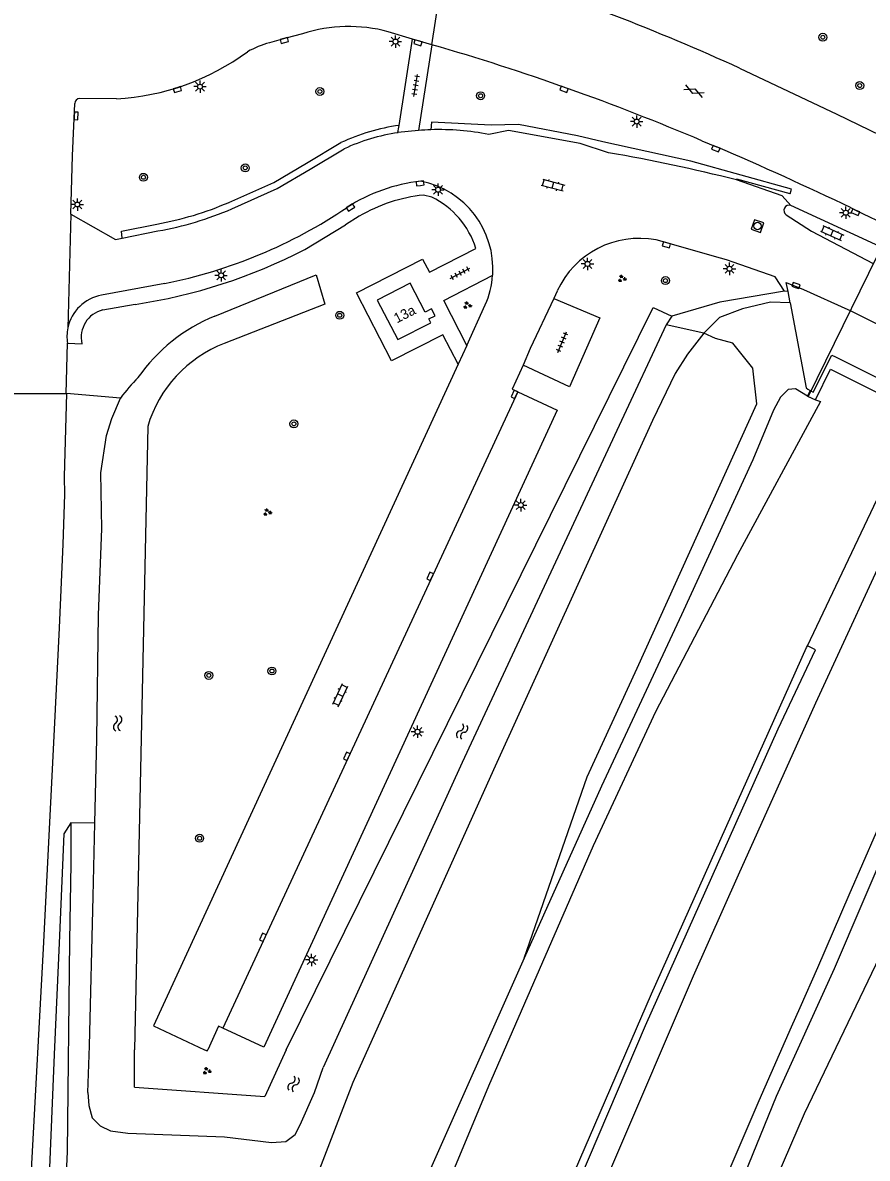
# Model space of a CAD drawing. Extents: x 137999 to 141000, y 397500 to 400501.
# Drawn here: x 138159.8 to 138245, y 398489.1 to 398603.5 of the extents above; entities that cross this region are included whole.
import ezdxf

# ---------------------------------------------------------------- set-up
doc = ezdxf.new("R2010")
doc.units = 0
for name, color, linetype in [('gg-anno-huisnummerreeks BGT', 7, 'Continuous'), ('gg-bbg-hoofdgebouw', 7, 'Continuous'), ('gg-knt-BGT kruinlijn', 7, 'Continuous'), ('gg-knt-bronhoudergrens niveau 01', 7, 'Continuous'), ('gg-knt-verharding', 7, 'Continuous'), ('gg-knt-verharding nz', 7, 'Continuous'), ('gg-kntw-bovenkant insteek waterloop', 7, 'Continuous'), ('gt-grn-groengrens', 7, 'Continuous'), ('gt-grn-weggrens', 7, 'Continuous'), ('gt-symb-boom', 7, 'Continuous'), ('gt-symb-gesloten verharding', 7, 'Continuous'), ('gt-symb-groenvak', 7, 'Continuous'), ('gt-symb-klinker verharding', 7, 'Continuous'), ('gt-symb-kolk', 7, 'Continuous'), ('gt-symb-lichtmast', 7, 'Continuous'), ('gt-symb-rioolschacht', 7, 'Continuous'), ('gt-symb-tegel verharding', 7, 'Continuous'), ('gt-symb-watersymbool', 7, 'Continuous'), ('gx-grn-maaiveld', 7, 'Continuous')]:
    doc.layers.add(name, color=color, linetype=linetype)

# ---------------------------------------------------------------- blocks, each defined once
blk = doc.blocks.new('gt0-KOLK')
at = {"layer": 'gt-symb-kolk'}
blk.add_lwpolyline([(0, 0), (0.37, 0), (0.37, 0.4), (-0.38, 0.4), (-0.38, 0), (0, 0)], dxfattribs=at)
blk = doc.blocks.new('gt0-LMAST')
at = {"layer": 'gt-symb-lichtmast'}
for p, q in [((-0.18, 0.17), (-0.45, 0.44)), ((0, 0.25), (0, 0.62)), ((0.17, 0.17), (0.44, 0.44)), ((-0.25, 0), (-0.63, 0)), ((-0.18, -0.18), (-0.45, -0.45)), ((0, -0.25), (0, -0.63)), ((0.44, -0.45), (0.17, -0.18)), ((0.25, 0), (0.62, 0))]:
    blk.add_line(p, q, dxfattribs=at)
blk.add_circle((0, 0), 0.25, dxfattribs=at)
blk = doc.blocks.new('gt0-BOOM')
at = {"layer": 'gt-symb-boom'}
for radius in [0.4, 0.2]:
    blk.add_circle((0, 0), radius, dxfattribs=at)
blk = doc.blocks.new('gt0-TEG1')
at = {"layer": 'gt-symb-tegel verharding'}
for p, q in [((-1.13, 0), (1.12, 0)), ((-0.9, -0.25), (-0.9, 0.25)), ((-0.45, -0.25), (-0.45, 0.25)), ((0, -0.25), (0, 0.25)), ((0.45, -0.25), (0.45, 0.25)), ((0.9, -0.25), (0.9, 0.25))]:
    blk.add_line(p, q, dxfattribs=at)
blk = doc.blocks.new('gt0-KL1')
at = {"layer": 'gt-symb-klinker verharding'}
for p, q in [((-1.15, 0.3), (1.15, 0.3)), ((-1, -0.3), (-1, 0.3)), ((-0.5, 0.3), (-0.5, 0.45)), ((0, -0.3), (0, 0.3)), ((0.5, 0.3), (0.5, 0.45)), ((1, -0.3), (1, 0.3)), ((-1.15, -0.3), (1.15, -0.3)), ((-0.5, -0.45), (-0.5, -0.3)), ((0.5, -0.45), (0.5, -0.3))]:
    blk.add_line(p, q, dxfattribs=at)
blk = doc.blocks.new('gt0-GESVH1')
at = {"layer": 'gt-symb-gesloten verharding'}
for p, q in [((-0.99, -0.26), (0.01, 0.24)), ((0.01, -0.26), (-0.99, 0.24)), ((0.01, 0.24), (1.01, -0.26)), ((1.01, 0.24), (0.01, -0.26))]:
    blk.add_line(p, q, dxfattribs=at)
blk = doc.blocks.new('gt0-GRVAK')
at = {"layer": 'gt-symb-groenvak'}
for p, q in [((-0.11, 0.19), (-0.23, 0.24)), ((-0.18, 0.15), (0.09, 0.15)), ((-0.09, 0.21), (-0.16, 0.32)), ((-0.05, 0.21), (-0.05, 0.39)), ((0, 0.21), (0.06, 0.32)), ((0.02, 0.19), (0.13, 0.24)), ((0.26, -0.05), (0.2, 0.06)), ((0.31, -0.05), (0.31, 0.13)), ((0.35, -0.05), (0.41, 0.06)), ((-0.24, -0.23), (-0.36, -0.18)), ((-0.32, -0.26), (-0.05, -0.26)), ((-0.23, -0.21), (-0.29, -0.09)), ((-0.18, -0.2), (-0.18, -0.02)), ((-0.14, -0.21), (-0.07, -0.09)), ((-0.12, -0.23), (0, -0.18)), ((0.24, -0.07), (0.12, -0.02)), ((0.17, -0.11), (0.44, -0.11)), ((0.37, -0.07), (0.49, -0.02))]:
    blk.add_line(p, q, dxfattribs=at)
blk = doc.blocks.new('gt0-RS')
at = {"layer": 'gt-symb-rioolschacht'}
blk.add_lwpolyline([(-0.5, -0.5), (0.5, -0.5), (0.5, 0.5), (-0.5, 0.5)], close=True, dxfattribs=at)
blk.add_circle((0, 0), 0.375, dxfattribs=at)
blk = doc.blocks.new('gt0-WA')
at = {"layer": 'gt-symb-watersymbool'}
for centre, start, end in [((-0.32, 0.02), 28.0725, 151.9275), ((0.43, 0.42), 208.0725, 331.9275), ((-0.32, -0.43), 28.0725, 151.9275), ((0.43, -0.03), 208.0725, 331.9275)]:
    blk.add_arc(centre, 0.425, start, end, dxfattribs=at)

msp = doc.modelspace()

# ---------------------------------------------------------------- linework, layer by layer
at = {"layer": 'gg-bbg-hoofdgebouw'}
msp.add_lwpolyline([(138197.65, 398571.59), (138200.97, 398573.27), (138200.77, 398573.66), (138201.41, 398573.99), (138201.04, 398574.69), (138200.4, 398574.36), (138198.9, 398577.26), (138195.57, 398575.56), (138197.65, 398571.59)], dxfattribs=at)
at = {"layer": 'gg-knt-BGT kruinlijn'}
for p, q in [((138239.49, 398566.29), (138241.37, 398570.01)), ((138241.37, 398570.01), (138241.74, 398569.83)), ((138241.74, 398569.83), (138250.7, 398565.38)), ((138236.23, 398565.78), (138235.5, 398564.47)), ((138236.98, 398566.54), (138236.23, 398565.78)), ((138237.71, 398566.62), (138236.98, 398566.54)), ((138238.95, 398565.88), (138237.71, 398566.62)), ((138239.21, 398566.45), (138238.95, 398565.88)), ((138239.21, 398566.45), (138239.27, 398566.42)), ((138239.27, 398566.42), (138239.49, 398566.29)), ((138235.5, 398564.47), (138233.42, 398559.46)), ((138233.42, 398559.46), (138226.22, 398543.85)), ((138226.22, 398543.85), (138218.17, 398526.58)), ((138218.17, 398526.58), (138210.38, 398509.23)), ((138164.68, 398522.89), (138164, 398521.77)), ((138241.67, 398508.18), (138247.8, 398522.61)), ((138164, 398521.77), (138163.56, 398511.53)), ((138163.56, 398511.53), (138163.01, 398499.51)), ((138210.38, 398509.23), (138198.18, 398481.84)), ((138235.81, 398495.33), (138241.67, 398508.18)), ((138163.01, 398499.51), (138162.34, 398483.26)), ((138229.04, 398478.7), (138235.81, 398495.33))]:
    msp.add_line(p, q, dxfattribs=at)
at = {"layer": 'gg-knt-bronhoudergrens niveau 01'}
for points in [[(138268.99, 398624.37), (138268.26, 398624.74), (138256.39, 398601.32), (138238.99, 398565.86), (138239.73, 398565.5)], [(138239.73, 398565.5), (138241.24, 398568.59), (138242.92, 398567.76), (138246.23, 398566.12), (138249.47, 398564.52), (138250.08, 398564.21)]]:
    msp.add_lwpolyline(points, dxfattribs=at)
at = {"layer": 'gg-knt-verharding'}
for p, q in [((138199.14, 398601.88), (138196.69, 398602.61)), ((138197.78, 398593.17), (138199.14, 398601.88)), ((138201.09, 398601.31), (138199.14, 398601.88)), ((138201.09, 398601.31), (138199.74, 398592.66)), ((138169.28, 398595.86), (138165.61, 398595.88)), ((138197.75, 398593), (138197.78, 398593.17)), ((138197.66, 398592.45), (138197.75, 398593)), ((138199.74, 398592.66), (138197.66, 398592.45)), ((138228.29, 398591.62), (138229.77, 398591.01)), ((138201.08, 398585.95), (138200.24, 398586.15)), ((138164.69, 398584.23), (138164.39, 398572.75)), ((138193.75, 398584.02), (138192.37, 398583.14)), ((138246.24, 398580.98), (138237.26, 398585.09)), ((138188.27, 398580.67), (138192.37, 398583.14)), ((138169.88, 398581.81), (138173.47, 398582.53)), ((138230.17, 398579.8), (138223.67, 398581.63)), ((138174.15, 398577.23), (138167.79, 398576.06)), ((138213.7, 398576.48), (138213.36, 398575.74)), ((138167.93, 398574.58), (138171.18, 398575.14)), ((138204.61, 398570.99), (138206.46, 398575.08)), ((138164.23, 398566.15), (138164.36, 398571.21)), ((138164.36, 398571.21), (138165.82, 398571.17)), ((138204.61, 398570.99), (138203.74, 398569.11))]:
    msp.add_line(p, q, dxfattribs=at)
for points in [[(138188.05, 398602.4), (138186.37, 398601.98), (138184.71, 398601.51)], [(138232.09, 398598.95), (138241.89, 398594.3), (138250.61, 398590.07), (138250.85, 398590.03)], [(138164.69, 398584.23), (138164.85, 398590.11), (138165.08, 398595.37)], [(138218.89, 398590.41), (138216.02, 398591.34), (138208.81, 398592.65), (138206.82, 398592.24)], [(138180.92, 398584.77), (138185.47, 398586.8), (138188.81, 398588.75), (138192.24, 398590.82)], [(138237.26, 398585.09), (138236.37, 398586.07), (138231.77, 398587.68)], [(138164.69, 398584.23), (138169.18, 398581.67), (138169.88, 398581.81)], [(138236.79, 398584.16), (138239.35, 398582.51), (138245.55, 398579.27)], [(138243.32, 398584.85), (138243.85, 398584.61), (138247.22, 398582.97)], [(138203.74, 398569.11), (138202.17, 398572.07), (138197, 398569.44), (138193.48, 398576.28), (138200.13, 398579.7), (138200.83, 398578.39), (138205.51, 398580.78)], [(138236.61, 398576.48), (138235.69, 398577.9), (138230.76, 398579.63), (138230.17, 398579.8)], [(138204.61, 398570.99), (138202.28, 398575.54), (138207.21, 398578.07)], [(138236.61, 398576.48), (138230.09, 398575.35), (138225.27, 398573.94)], [(138213.36, 398575.74), (138218.02, 398573.77), (138214.95, 398566.83), (138210.27, 398569.01)], [(138213.36, 398575.74), (138210.98, 398570.68), (138210.27, 398569.01)], [(138203.74, 398569.11), (138173.02, 398502.42), (138178.16, 398500)], [(138210.27, 398569.01), (138209.16, 398566.6), (138209.74, 398566.32)], [(138209.74, 398566.32), (138213.71, 398564.48), (138184.15, 398500.25), (138180.01, 398502.18)], [(138180.01, 398502.18), (138179.58, 398502.38), (138178.49, 398500)], [(138178.16, 398500), (138178.43, 398499.88), (138178.49, 398500)]]:
    msp.add_lwpolyline(points, dxfattribs=at)
for centre, radius, start, end in [((138129.33, 398372.28), 248.87, 65.6132, 71.9242), ((138192.72, 398588), 15.14, 74.802, 107.9574), ((138187.85, 398590.65), 11.3, 106.1152, 118.27), ((138134.16, 398370.18), 240.62, 66.969, 73.8496), ((138168.02, 398620.17), 24.34, 272.9631, 306.4879), ((138165.61, 398595.35), 0.53, 90.1409, 178.4309), ((138200.62, 398572.73), 19.93, 98.5276, 114.869), ((138201.76, 398569.25), 23.49, 91.8827, 94.9518), ((138201.84, 398568.13), 24.62, 78.3446, 91.9799), ((138094.1, 398274.56), 344.31, 64.3169, 66.7933), ((138189.22, 398418.73), 174.23, 75.8634, 80.1962), ((138201.75, 398570.8), 16.84, 96.1592, 123.1239), ((138198.22, 398578.7), 9.01, 355.9911, 78.956), ((138201.99, 398569.85), 16.39, 96.1206, 120.1765), ((138197.27, 398578.19), 8.64, 17.4528, 63.7936), ((138237.08, 398584.6), 0.525, 69.2079, 236.7284), ((138167.66, 398615.38), 33.36, 280.0294, 293.4143), ((138164.05, 398627.31), 51.09, 281.3971, 303.8926), ((138221.99, 398572.67), 9.12, 79.3529, 155.2893), ((138162.93, 398629.74), 55.23, 278.5946, 297.3045), ((138198.02, 398578.78), 9.21, 336.3355, 355.5649), ((138168.55, 398571.88), 4.25, 100.3016, 168.1259), ((138168.59, 398571.81), 2.85, 103.5604, 193.0675), ((138168.54, 398571.88), 4.24, 168.08, 189.0167)]:
    msp.add_arc(centre, radius, start, end, dxfattribs=at)
at = {"layer": 'gg-knt-verharding nz'}
msp.add_line((138209.74, 398566.32), (138180.01, 398502.18), dxfattribs=at)
at = {"layer": 'gg-kntw-bovenkant insteek waterloop'}
for p, q in [((138186.4, 398500), (138223.38, 398574.83)), ((138223.38, 398574.83), (138225.27, 398573.94)), ((138225.27, 398573.94), (138224.69, 398573.07)), ((138172.44, 398562.81), (138171.11, 398500)), ((138171.11, 398496.22), (138171.11, 398500)), ((138186.4, 398500), (138184.23, 398495.3)), ((138171.11, 398496.22), (138184.23, 398495.3)), ((138166.41, 398495.68), (138166.51, 398494.4))]:
    msp.add_line(p, q, dxfattribs=at)
for points in [[(138179.21, 398573.94), (138189.42, 398578.11), (138190.3, 398575.14), (138180.15, 398571.2)], [(138224.69, 398573.07), (138219.96, 398562.94), (138204.14, 398528.97), (138190.11, 398498.22)], [(138186.37, 398490.77), (138187.31, 398491.46), (138187.82, 398492.44), (138189.24, 398495.7), (138190.11, 398498.22)], [(138166.51, 398494.4), (138166.84, 398493.15), (138167.65, 398492.32), (138168.68, 398491.84), (138170.42, 398491.59), (138180.18, 398491.23), (138184.9, 398490.67), (138186.37, 398490.77)]]:
    msp.add_lwpolyline(points, dxfattribs=at)
for centre, radius, start, end in [((138185.86, 398557.66), 17.59, 112.2194, 144.9503), ((138184.83, 398559.16), 12.92, 111.2225, 163.5639), ((138185.3, 398554.22), 19.36, 135.6027, 143.6522)]:
    msp.add_arc(centre, radius, start, end, dxfattribs=at)
at = {"layer": 'gt-grn-groengrens'}
for points in [[(138237.19, 398586.26), (138237.32, 398586.74), (138227.17, 398589.57), (138218.3, 398591.52), (138215.77, 398592.12), (138209.82, 398593.25), (138207.05, 398593.21), (138201.03, 398593.51), (138200.99, 398592.73)], [(138180.63, 398585.41), (138185.15, 398587.42), (138188.45, 398589.35), (138191.91, 398591.44)], [(138237.19, 398586.26), (138231.8, 398587.76), (138231.77, 398587.68)], [(138169.88, 398581.81), (138169.8, 398582.51), (138173.35, 398583.22)]]:
    msp.add_lwpolyline(points, dxfattribs=at)
for centre, radius, start, end in [((138200.63, 398572.71), 20.66, 97.9344, 114.9673), ((138167.68, 398615.32), 32.59, 280.0221, 293.4211)]:
    msp.add_arc(centre, radius, start, end, dxfattribs=at)
at = {"layer": 'gt-grn-weggrens'}
msp.add_line((138201.09, 398601.31), (138202.41, 398610.05), dxfattribs=at)
at = {"layer": 'gx-grn-maaiveld'}
for p, q in [((138236.97, 398576.43), (138236.61, 398576.48)), ((138237.19, 398575.3), (138236.97, 398576.43)), ((138243.24, 398574.51), (138243.9, 398574.18)), ((138243.9, 398574.18), (138252.82, 398569.74)), ((138228.47, 398572.22), (138224.69, 398573.07)), ((138156.81, 398566.14), (138164.23, 398566.15)), ((138164.27, 398566.15), (138164.23, 398566.15)), ((138169.71, 398565.69), (138164.27, 398566.15)), ((138238.95, 398565.88), (138239.73, 398565.5)), ((138238.93, 398540.73), (138250.08, 398564.21)), ((138167.11, 398522.83), (138164.68, 398522.89))]:
    msp.add_line(p, q, dxfattribs=at)
for points in [[(138236.97, 398576.43), (138236.8, 398577.34), (138238.54, 398576.63), (138243.01, 398574.62), (138243.24, 398574.51)], [(138237.19, 398575.3), (138235.21, 398575.35), (138232.38, 398574.7), (138230.08, 398573.81), (138228.47, 398572.22)], [(138237.19, 398575.3), (138238.81, 398566.72), (138238.98, 398566.58), (138239.21, 398566.45)], [(138228.47, 398572.22), (138226.84, 398570.13), (138225.6, 398568.17), (138223.32, 398563.43), (138218.86, 398553.61), (138207.28, 398528.22), (138193.11, 398496.72), (138184.46, 398474.17), (138179.23, 398455.53)], [(138210.38, 398509.23), (138216.73, 398527.51), (138221.78, 398538.48), (138233.83, 398565.12), (138233.43, 398568.71), (138231.42, 398571.23), (138229.66, 398571.68), (138228.47, 398572.22)], [(138164.27, 398566.15), (138164.01, 398557.79), (138164.05, 398555.97), (138163.9, 398550.97), (138163.51, 398542.53), (138163.02, 398532.29), (138161.92, 398510.22), (138160.74, 398488.52), (138159.93, 398469.65)], [(138167.11, 398522.83), (138167.32, 398531.35), (138167.48, 398543.85), (138167.82, 398552.52), (138167.73, 398558.16), (138168.3, 398561.91), (138168.83, 398563.62), (138169.71, 398565.69)], [(138239.73, 398565.5), (138240.25, 398565.35), (138231.87, 398549.89), (138223.62, 398534.07), (138217.33, 398520.55), (138206.8, 398496.33), (138187.27, 398449.47)], [(138199.35, 398440.3), (138202.4, 398447.99), (138212.07, 398471.41), (138219.4, 398488.71), (138227.45, 398507.44), (138231.99, 398517.62), (138239.78, 398534.97), (138248.2, 398553.24), (138252.48, 398562.64), (138252.66, 398562.93)], [(138208.51, 398433.6), (138211.57, 398441.26), (138214.46, 398448.32), (138218.32, 398457.71), (138221.48, 398465.3), (138224.35, 398472.07), (138227.4, 398479.25), (138231.44, 398488.78), (138234.08, 398494.9), (138237.33, 398502.33), (138238.18, 398504.26), (138239.96, 398508.3), (138243.12, 398515.61), (138245.89, 398521.93), (138247.84, 398526.51), (138251.96, 398537.27), (138252.94, 398539.62), (138253.75, 398541.64), (138256.98, 398549.73), (138261.33, 398558.64)], [(138212.52, 398430.64), (138213.68, 398434.19), (138219.34, 398448.29), (138225.25, 398462.6), (138231.64, 398477.4), (138238.62, 398493.59), (138247.43, 398511.91), (138254.26, 398528.91), (138260.52, 398542.31), (138263.58, 398548.51), (138266.57, 398550.15), (138270.19, 398550.98), (138271.72, 398549.33), (138272.76, 398545.92)], [(138200.33, 398451.44), (138201.21, 398451.21), (138209.46, 398471.63), (138222.61, 398502.44), (138235.99, 398532.36), (138239.73, 398540.33), (138238.93, 398540.73)], [(138200.33, 398451.44), (138200.34, 398451.47), (138208.22, 398471), (138223.2, 398505.64), (138238.85, 398540.56), (138238.93, 398540.73)], [(138164.68, 398522.89), (138164.68, 398518.75), (138164.56, 398511.03), (138164.33, 398489.71), (138163.28, 398467.16)], [(138166.41, 398495.68), (138166.58, 398500.39), (138166.93, 398515.45), (138167.11, 398522.83)]]:
    msp.add_lwpolyline(points, dxfattribs=at)

# ---------------------------------------------------------------- block references
at = {"layer": 'gt-symb-boom'}
for p in [(138240.48, 398602.06), (138189.79, 398596.59), (138205.99, 398596.16), (138244.2, 398597.19), (138182.27, 398588.89), (138172.01, 398587.94), (138224.62, 398577.53), (138191.79, 398574.03), (138187.17, 398563.09), (138184.96, 398538.18), (138178.6, 398537.74), (138177.67, 398521.32)]:
    msp.add_blockref('gt0-BOOM', p, dxfattribs=at)
at = {"layer": 'gt-symb-gesloten verharding', "rotation": 156.17710050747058}
msp.add_blockref('gt0-GESVH1', (138227.5, 398596.61), dxfattribs=at)
at = {"layer": 'gt-symb-groenvak'}
for p in [(138220.23, 398577.73), (138204.64, 398575.04), (138184.49, 398554.18), (138178.39, 398497.87)]:
    msp.add_blockref('gt0-GRVAK', p, dxfattribs=at)
at = {"layer": 'gt-symb-klinker verharding'}
for p, rotation in [((138213.28, 398587.15), -15.00891367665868), ((138241.41, 398582.32), -24.643095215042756), ((138191.84, 398535.75), 64.97272120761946)]:
    msp.add_blockref('gt0-KL1', p, dxfattribs=dict(at, rotation=rotation))
at = {"layer": 'gt-symb-kolk'}
for p, rotation in [((138186.15, 398601.92), -164.75492966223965), ((138199.72, 398601.7), 162.96046487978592), ((138175.37, 398596.97), -162.41690287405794), ((138214.47, 398597), 160.4964267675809), ((138165.03, 398594.13), -92.57914750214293), ((138229.77, 398591.01), 157.4858873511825), ((138199.92, 398587.13), 7.004259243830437), ((138192.99, 398584.72), 32.005383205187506), ((138243.85, 398584.61), 154.97272120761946), ((138224.67, 398580.94), -15.71725244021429), ((138237.7, 398576.85), -19.32248237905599), ((138209.58, 398565.98), 65.10079947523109), ((138201.08, 398547.63), 65.10079947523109), ((138192.68, 398529.51), 65.10079947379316), ((138184.23, 398511.26), 65.10079947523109)]:
    msp.add_blockref('gt0-KOLK', p, dxfattribs=dict(at, rotation=rotation))
at = {"layer": 'gt-symb-lichtmast'}
for p in [(138197.41, 398601.62), (138177.71, 398597.08), (138221.72, 398593.56), (138201.7, 398586.69), (138165.35, 398585.2), (138242.79, 398584.37), (138216.77, 398579.21), (138179.84, 398578.06), (138231.08, 398578.72), (138210.04, 398554.9), (138199.63, 398532.06), (138188.96, 398509.06)]:
    msp.add_blockref('gt0-LMAST', p, dxfattribs=at)
at = {"layer": 'gt-symb-rioolschacht', "rotation": -19.32248237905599}
msp.add_blockref('gt0-RS', (138233.9, 398583.03), dxfattribs=at)
at = {"layer": 'gt-symb-tegel verharding'}
for p, rotation in [((138199.45, 398597.21), 80.56592086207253), ((138203.93, 398578.26), 27.974729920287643), ((138214.21, 398571.32), 66.97450798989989)]:
    msp.add_blockref('gt0-TEG1', p, dxfattribs=dict(at, rotation=rotation))
at = {"layer": 'gt-symb-watersymbool'}
for p, rotation in [((138169.41, 398532.85), 92.97967378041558), ((138204.1, 398532.03), 69.02828944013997), ((138187.12, 398496.51), 69.02828943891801)]:
    msp.add_blockref('gt0-WA', p, dxfattribs=dict(at, rotation=rotation))

# ---------------------------------------------------------------- texts
at = {"layer": 'gg-anno-huisnummerreeks BGT'}
msp.add_text('13a', height=1, rotation=27, dxfattribs=at).set_placement((138197.56, 398573.21))

doc.saveas('drawing.dxf')
